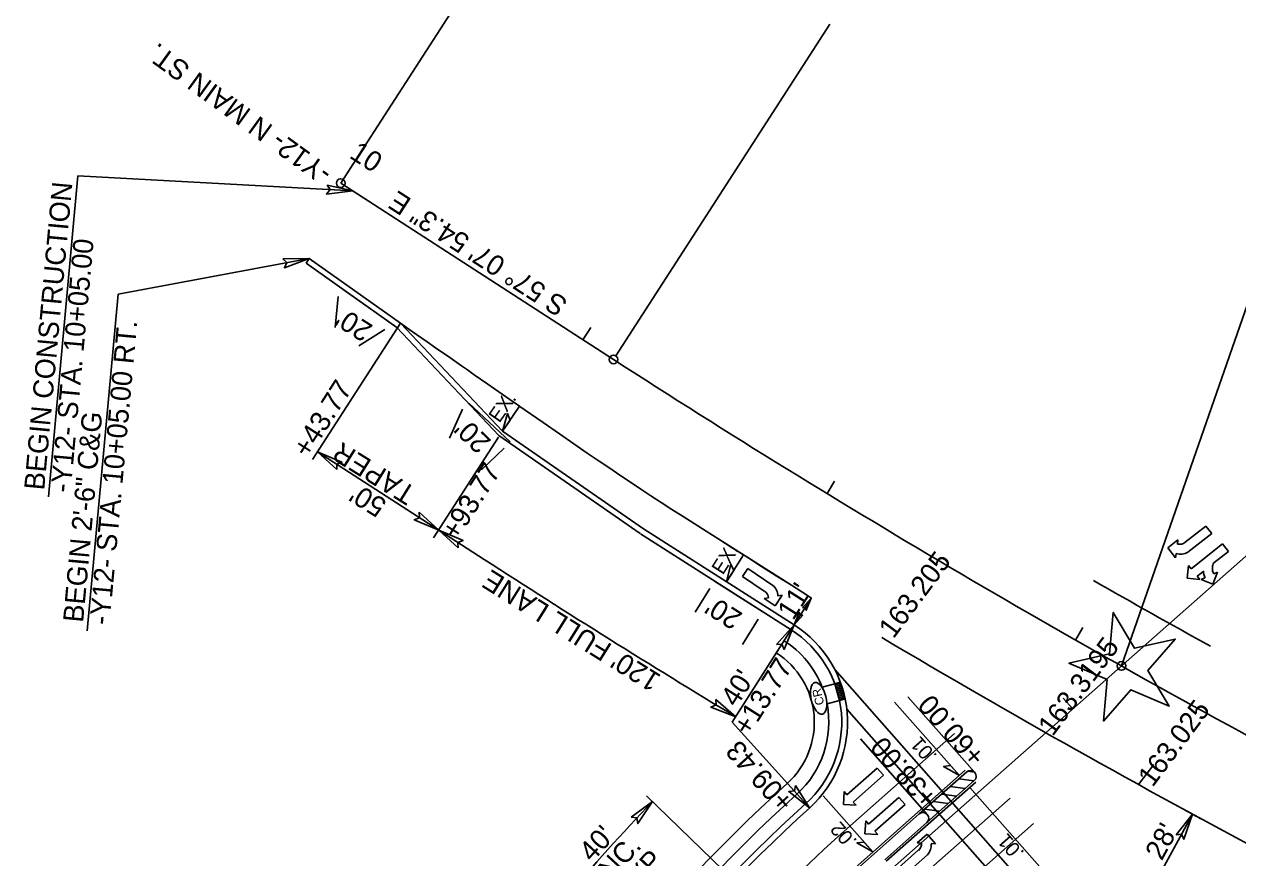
# Model space of a CAD drawing. Extents: x 2010838 to 2015151, y 441905 to 447792.
# Drawn here: x 2012526.5 to 2012947.2, y 446996.9 to 447285.7 of the extents above; entities that cross this region are included whole.
import ezdxf

# ---------------------------------------------------------------- set-up
doc = ezdxf.new("R2010")
doc.units = 0
for name, color, linetype in [('A-Wall-Abov', 7, 'Continuous'), ('A-Wall-Blow', 7, 'Continuous'), ('A-Wall-Comp', 7, 'Continuous'), ('B-Border', 7, 'Continuous'), ('B-Sheet Number', 7, 'Continuous'), ('C-Alignment Geometry', 7, 'Continuous'), ('C-Building', 7, 'Continuous'), ('C-CURB STOPS', 7, 'Continuous'), ('C-EOP 1', 7, 'Continuous'), ('C-Grave Plots', 7, 'Continuous'), ('C-SHBD-TEXT', 7, 'Continuous'), ('CLRD', 7, 'Continuous'), ('Cont-2-Lidar', 7, 'Continuous'), ('Default_10ft_LIDAR_Contou', 7, 'Continuous'), ('Default_2FT_LIDAR_Contour', 7, 'Continuous'), ('HATCH', 7, 'Continuous'), ('s-Existing Major', 7, 'Continuous'), ('S-Existing Minor', 7, 'Continuous'), ('S-overhead electric', 7, 'Continuous'), ('TEXT', 7, 'Continuous'), ('TEXT-LG', 7, 'Continuous'), ('TEXT-MED', 7, 'Continuous'), ('X2', 7, 'Continuous'), ('X4', 7, 'Continuous')]:
    doc.layers.add(name, color=color, linetype=linetype)

msp = doc.modelspace()

# ---------------------------------------------------------------- linework, layer by layer
at = {"layer": 'A-Wall-Abov'}
for p, q in [((2012928.92, 447106.22), (2012936.15, 447111.83)), ((2012936.15, 447111.83), (2012938.17, 447109.23)), ((2012922.9, 447104.27), (2012926.43, 447107.07)), ((2012926.43, 447107.07), (2012926.24, 447105.6)), ((2012938.17, 447109.23), (2012929.84, 447102.76)), ((2012941.85, 447105.64), (2012931.07, 447097.02)), ((2012943.91, 447103.06), (2012941.85, 447105.64)), ((2012925.64, 447100.83), (2012922.9, 447104.27)), ((2012925.82, 447102.3), (2012925.64, 447100.83)), ((2012938.87, 447099.03), (2012943.91, 447103.06)), ((2012930.13, 447098.19), (2012929.68, 447093.79)), ((2012931.07, 447097.02), (2012930.13, 447098.19)), ((2012775.43, 447094.39), (2012777.27, 447097.14)), ((2012783.03, 447089.3), (2012775.43, 447094.39)), ((2012777.27, 447097.14), (2012786.03, 447091.26)), ((2012929.68, 447093.79), (2012934.07, 447093.27)), ((2012933.13, 447094.44), (2012935.36, 447096.22)), ((2012934.07, 447093.27), (2012933.13, 447094.44)), ((2012935.81, 447093.89), (2012934.43, 447093.3)), ((2012934.43, 447093.3), (2012938.55, 447091.67)), ((2012938.55, 447091.67), (2012940.18, 447095.79)), ((2012940.18, 447095.79), (2012938.84, 447095.23)), ((2012783.01, 447086.67), (2012784.47, 447086.95)), ((2012786.78, 447084.2), (2012783.01, 447086.67)), ((2012789.19, 447087.89), (2012786.78, 447084.2)), ((2012787.73, 447087.6), (2012789.19, 447087.89)), ((2012811.69, 447018.67), (2012822.19, 447027.94)), ((2012822.19, 447027.94), (2012824.37, 447025.46)), ((2012824.37, 447025.46), (2012813.88, 447016.2)), ((2012810.45, 447015.31), (2012810.7, 447019.8)), ((2012810.7, 447019.8), (2012811.69, 447018.67)), ((2012819.17, 447008.52), (2012829.66, 447017.79)), ((2012829.66, 447017.79), (2012831.85, 447015.31)), ((2012814.87, 447015.07), (2012810.45, 447015.31)), ((2012813.88, 447016.2), (2012814.87, 447015.07)), ((2012831.85, 447015.31), (2012821.35, 447006.05)), ((2012817.93, 447005.16), (2012818.18, 447009.65)), ((2012818.18, 447009.65), (2012819.17, 447008.52)), ((2012822.35, 447004.92), (2012817.93, 447005.16)), ((2012821.35, 447006.05), (2012822.35, 447004.92)), ((2012839.46, 447005.02), (2012836.05, 447002.07)), ((2012842.33, 447001.68), (2012839.46, 447005.02)), ((2012836.05, 447002.07), (2012837.53, 447001.98)), ((2012840.85, 447001.78), (2012842.33, 447001.68)), ((2012836.42, 446999.47), (2012829.56, 446993.41)), ((2012831.75, 446990.94), (2012839.65, 446997.92))]:
    msp.add_line(p, q, dxfattribs=at)
for centre, radius, start, end in [((2012926.91, 447108.79), 3.28, 258.1586, 307.8167), ((2012927.29, 447107.33), 5.25, 253.829, 299.1407), ((2012942.8, 447097.24), 4.43, 176.0895, 206.9431), ((2012940.9, 447097.52), 2.52, 143.2676, 179.5796), ((2012939.77, 447095.92), 4.43, 176.1833, 207.0619), ((2012781.23, 447086.59), 3.28, 6.5226, 56.1808), ((2012782.49, 447087.4), 5.25, 2.193, 47.5047), ((2012834.27, 447001.92), 3.28, 311.4451, 1.1033), ((2012835.63, 447001.27), 5.25, 320.1212, 5.4329)]:
    msp.add_arc(centre, radius, start, end, dxfattribs=at)
at = {"layer": 'A-Wall-Blow'}
for p, q in [((2012698.21, 447153.33), (2012692.25, 447144.74)), ((2012775.88, 447101.83), (2012769.95, 447092.49)), ((2012850.65, 447025.37), (2012828.15, 447050.85)), ((2012803.39, 447018.33), (2012820.64, 446998.89)), ((2012881.11, 446990.87), (2012854.28, 447021.26))]:
    msp.add_line(p, q, dxfattribs=at)
at = {"layer": 'A-Wall-Comp'}
for points in [[(2012692.25, 447144.74), (2012694.03, 447150.81), (2012694.89, 447148.54)], [(2012769.95, 447092.49), (2012771.48, 447098.63), (2012772.43, 447096.4)], [(2012850.65, 447025.37), (2012845.18, 447028.54), (2012847.59, 447028.83)], [(2012820.64, 446998.89), (2012815.16, 447002.05), (2012817.57, 447002.35)]]:
    msp.add_lwpolyline(points, close=True, dxfattribs=at)
at = {"layer": 'B-Border'}
for radius, start, end in [(3308.24, 240.27502, 241.0786), (3362.24, 239.35482, 242.0055)]:
    msp.add_arc((2014537.56, 449965.84), radius, start, end, dxfattribs=at)
at = {"layer": 'B-Sheet Number'}
for p, q in [((2012635.31, 447191.33), (2012634.29, 447180.66)), ((2012635.31, 447191.33), (2012635.31, 447191.33)), ((2012651.47, 447179.9), (2012642.48, 447174.24)), ((2012651.47, 447179.9), (2012651.47, 447179.9))]:
    msp.add_line(p, q, dxfattribs=at)
at = {"layer": 'C-Alignment Geometry'}
for p, q in [((2012873.97, 446986.8), (2012807.45, 447062.13)), ((2012868.96, 446983.42), (2012811.63, 447048.33)), ((2012853.19, 447026.64), (2012836.7, 447012.08)), ((2012853.46, 447026.84), (2012855.99, 447026.5)), ((2012839.35, 447009.08), (2012855.84, 447023.65)), ((2012847.48, 447021.6), (2012852.72, 447020.89)), ((2012850.45, 447024.22), (2012855.69, 447023.51)), ((2012844.51, 447018.98), (2012849.75, 447018.26)), ((2012838.57, 447013.73), (2012843.8, 447013.02)), ((2012841.54, 447016.35), (2012846.78, 447015.64))]:
    msp.add_line(p, q, dxfattribs=at)
msp.add_arc((2012854.52, 447025.14), 2, 311.4451, 131.4451, dxfattribs=at)
at = {"layer": 'C-Building'}
for p, q in [((2012720.18, 447176.38), (2012722.89, 447180.58)), ((2012804.78, 447123.08), (2012807.38, 447127.35)), ((2012890.94, 447072.32), (2012893.41, 447076.67)), ((2012889.97, 447048.45), (2012886.66, 447052.2))]:
    msp.add_line(p, q, dxfattribs=at)
at = {"layer": 'C-CURB STOPS'}
for p, q in [((2012822.14, 446999.23), (2012836.7, 447012.08)), ((2012839.35, 447009.08), (2012824.79, 446996.23))]:
    msp.add_line(p, q, dxfattribs=at)
for centre, radius, start, end in [((2012838.03, 447010.58), 2, 311.4451, 131.4451), ((2013181.56, 446592.2), 543, 131.4451, 175.4266), ((2013181.56, 446592.2), 543, 131.4451, 175.4266)]:
    msp.add_arc(centre, radius, start, end, dxfattribs=at)
at = {"layer": 'C-EOP 1'}
msp.add_line((2012636.18, 447230.65), (2012640.53, 447237.37), dxfattribs=at)
at = {"layer": 'C-SHBD-TEXT'}
msp.add_line((2012912.8, 447022.24), (2012918.02, 447029.22), dxfattribs=at)
at = {"layer": 'CLRD'}
for p, q in [((2012636.18, 447230.65), (2012730.75, 447169.55)), ((2012636.18, 447230.65), (2012730.75, 447169.55)), ((2012827.44, 446993.23), (2013068.81, 447206.37))]:
    msp.add_line(p, q, dxfattribs=at)
msp.add_arc((2014537.56, 449965.84), 3329.24, 237.13174, 242.0055, dxfattribs=at)
msp.add_arc((2014537.56, 449965.84), 3329.24, 237.13174, 242.0055, dxfattribs=at)
at = {"layer": 'Default_10ft_LIDAR_Contou'}
for p, q in [((2012906.83, 447063.34), (2013011.33, 447363.33)), ((2012637, 447231.91), (2012711.21, 447346.77)), ((2012731.57, 447170.81), (2012805.78, 447285.67))]:
    msp.add_line(p, q, dxfattribs=at)
for centre in [(2012636.18, 447230.65), (2012730.75, 447169.55), (2012906.83, 447063.34)]:
    msp.add_circle(centre, 1.5, dxfattribs=at)
at = {"layer": 'HATCH'}
for p, q in [((2012792.47, 447091.3), (2012767.24, 447107.32)), ((2012813.7, 447008.78), (2012848.94, 447039.9)), ((2012821.65, 446999.79), (2012852.7, 447027.21)), ((2012825.29, 446995.66), (2012856.34, 447023.08)), ((2012833.23, 446986.67), (2012868.23, 447017.57)), ((2012841.17, 446977.67), (2012876.41, 447008.79))]:
    msp.add_line(p, q, dxfattribs=at)
for points in [[(2012656.91, 447182.17), (2012660.66, 447179.51), (2012666.12, 447175.67), (2012669.09, 447173.6), (2012673.98, 447170.19), (2012678.04, 447167.37), (2012680.15, 447165.89), (2012682.48, 447164.26), (2012687.19, 447160.99), (2012693.31, 447156.73), (2012698.21, 447153.33)], [(2012697.93, 447153.52), (2012706.33, 447147.7), (2012711.98, 447143.77), (2012717.03, 447140.27), (2012721.66, 447137.12), (2012725.82, 447134.3), (2012729.48, 447131.82), (2012732.97, 447129.46), (2012736.63, 447126.99), (2012740.27, 447124.55), (2012743.74, 447122.27), (2012747.24, 447120), (2012750.98, 447117.61), (2012754.86, 447115.15), (2012758.77, 447112.67), (2012762.86, 447110.1), (2012767.24, 447107.32), (2012771.93, 447104.33), (2012776.96, 447101.1), (2012782.1, 447097.81), (2012787.15, 447094.61), (2012792.47, 447091.3), (2012797.66, 447087.97), (2012799.45, 447086.8)]]:
    msp.add_lwpolyline(points, dxfattribs=at)
for centre, radius, start, end in [((2014537.56, 449965.84), 3362.24, 241.41262, 241.52803), ((2013181.56, 446592.2), 555.75, 131.4451, 175.4266), ((2013181.56, 446592.2), 543.75, 131.4451, 175.4266)]:
    msp.add_arc(centre, radius, start, end, dxfattribs=at)
at = {"layer": 's-Existing Major'}
for points in [[(2012631.48, 447229.98), (2012640.38, 447227.94), (2012631.26, 447226.84), (2012632.5, 447228.38)], [(2012616.14, 447204.42), (2012625.27, 447204.55), (2012616.67, 447201.31), (2012617.51, 447203.1)], [(2012634.87, 447131.38), (2012628.15, 447137.57), (2012636.62, 447134), (2012634.79, 447133.28)], [(2012663.43, 447116.62), (2012670.15, 447110.43), (2012661.68, 447114), (2012663.51, 447114.72)], [(2012676.86, 447104.25), (2012670.15, 447110.43), (2012678.62, 447106.87), (2012676.78, 447106.15)], [(2012796.24, 447083.51), (2012799.31, 447086.89), (2012797.56, 447082.64), (2012797.19, 447083.55)], [(2012796.45, 447080.94), (2012793.38, 447077.56), (2012795.14, 447081.81), (2012795.5, 447080.89)], [(2012787.25, 447070.79), (2012793.38, 447077.56), (2012789.88, 447069.06), (2012789.15, 447070.89)], [(2012766.21, 447051.73), (2012773.11, 447045.74), (2012764.54, 447049.06), (2012766.35, 447049.83)], [(2012793.86, 447021.9), (2012798.76, 447014.19), (2012791.49, 447019.82), (2012793.45, 447020.05)], [(2012736.92, 447010.98), (2012744.3, 447016.36), (2012739.15, 447008.75), (2012738.8, 447010.69)], [(2012925.79, 447004.86), (2012931.45, 447012.02), (2012928.53, 447003.31), (2012927.68, 447005.08)]]:
    msp.add_lwpolyline(points, close=True, dxfattribs=at)
at = {"layer": 'S-Existing Minor'}
for p, q in [((2012534.84, 447121.97), (2012545.07, 447233.21)), ((2012640.38, 447227.94), (2012545.07, 447233.21)), ((2012625.27, 447204.55), (2012559, 447192.15)), ((2012559, 447192.15), (2012548.28, 447075.55)), ((2012626.39, 447134.84), (2012656.95, 447182.14)), ((2012668.41, 447107.74), (2012690.93, 447142.6)), ((2012628.15, 447137.57), (2012670.15, 447110.43)), ((2012670.15, 447110.43), (2012685.95, 447100.22)), ((2012799.31, 447086.89), (2012793.38, 447077.56)), ((2012793.38, 447077.56), (2012771.89, 447043.83)), ((2012856.02, 447026.47), (2012832.85, 447052.7)), ((2012771.89, 447043.83), (2012798.76, 447014.19)), ((2012839.53, 447011.91), (2012816.36, 447038.14)), ((2012772.61, 446988.9), (2012742.23, 447018.37)), ((2012931.45, 447012.02), (2012918.08, 446987.42))]:
    msp.add_line(p, q, dxfattribs=at)
for centre, radius, start, end in [((2014537.56, 449965.84), 3411.78, 237.13174, 238.85785), ((2013182.44, 446591.46), 610.33, 135.8789, 140.15462)]:
    msp.add_arc(centre, radius, start, end, dxfattribs=at)
at = {"layer": 'S-overhead electric'}
for p, q in [((2012656.95, 447182.14), (2012625.27, 447204.55)), ((2012656.95, 447182.14), (2012692.29, 447144.7)), ((2012678.44, 447152.36), (2012673.88, 447142.32)), ((2012692.29, 447144.7), (2012741.15, 447110.84)), ((2012692.87, 447138.82), (2012685.02, 447131.24)), ((2012741.15, 447110.84), (2012793.38, 447077.56)), ((2012764.18, 447090.24), (2012759.09, 447081.98)), ((2012780.87, 447079.61), (2012775.52, 447070.81))]:
    msp.add_line(p, q, dxfattribs=at)
for centre, radius, start, end in [((2012771.89, 447043.83), 40, 312.2108, 57.4949), ((2013181.56, 446592.2), 569.75, 132.2108, 169.9194)]:
    msp.add_arc(centre, radius, start, end, dxfattribs=at)
at = {"layer": 'TEXT'}
msp.add_lwpolyline([(2012901.89, 447058.6), (2012900.58, 447044.24), (2012910.08, 447055.09), (2012923.36, 447049.38), (2012915.97, 447061.8), (2012925.48, 447072.66), (2012911.41, 447069.47), (2012904.03, 447081.87), (2012902.71, 447067.5), (2012888.62, 447064.3), (2012901.89, 447058.6)], dxfattribs=at)
at = {"layer": 'TEXT-LG'}
for p, q in [((2012807.47, 447057.19), (2012803.12, 447055.94)), ((2012807.47, 447057.19), (2012809.39, 447057.75)), ((2012807.47, 447057.19), (2012809.13, 447051.43)), ((2012809.39, 447057.75), (2012811.05, 447051.98)), ((2012809.13, 447051.43), (2012804.78, 447050.18)), ((2012811.05, 447051.98), (2012809.13, 447051.43))]:
    msp.add_line(p, q, dxfattribs=at)
for centre in [(2012807.82, 447056.89), (2012807.98, 447056.34), (2012808.14, 447055.76), (2012808.3, 447055.21), (2012808.35, 447057.05), (2012808.51, 447056.5), (2012808.67, 447055.92), (2012808.8, 447057.17), (2012808.83, 447055.37), (2012808.95, 447056.62), (2012809.12, 447056.05), (2012809.21, 447057.3), (2012809.28, 447055.49), (2012809.36, 447056.75), (2012809.53, 447056.17), (2012809.69, 447055.62), (2012808.47, 447054.63), (2012808.64, 447054.05), (2012808.8, 447053.47), (2012808.96, 447052.92), (2012809, 447054.79), (2012809.12, 447052.34), (2012809.17, 447054.21), (2012809.28, 447051.79), (2012809.33, 447053.63), (2012809.44, 447054.92), (2012809.49, 447053.08), (2012809.61, 447054.33), (2012809.65, 447052.5), (2012809.77, 447053.75), (2012809.81, 447051.95), (2012809.85, 447055.04), (2012809.93, 447053.2), (2012810.02, 447054.46), (2012810.1, 447052.63), (2012810.18, 447053.88), (2012810.25, 447052.07), (2012810.34, 447053.33), (2012810.51, 447052.75), (2012810.66, 447052.2)]:
    msp.add_circle(centre, 0.0869, dxfattribs=at)
for centre, radius, start, end in [((2012771.89, 447043.83), 33.5, 21.203, 57.4949), ((2012771.89, 447043.83), 28.5, 312.2108, 57.4949), ((2012771.89, 447043.83), 33.5, 312.2108, 10.9281), ((2013181.56, 446592.2), 581.25, 132.20083, 172.15843), ((2013181.56, 446592.2), 576.25, 132.20083, 171.53405)]:
    msp.add_arc(centre, radius, start, end, dxfattribs=at)
at = {"layer": 'TEXT-MED'}
for p, q in [((2012625.27, 447204.55), (2012624.19, 447202.87)), ((2012655.63, 447180.63), (2012624.19, 447202.87)), ((2012655.63, 447180.63), (2012690.98, 447143.18)), ((2012690.98, 447143.18), (2012740.01, 447109.2)), ((2012740.08, 447109.16), (2012792.31, 447075.87))]:
    msp.add_line(p, q, dxfattribs=at)
for centre, radius, start, end in [((2012771.89, 447043.83), 38, 312.2108, 57.4949), ((2013181.56, 446592.2), 571.75, 132.2008, 169.9194)]:
    msp.add_arc(centre, radius, start, end, dxfattribs=at)
at = {"layer": 'X2'}
for p, q in [((2012653.2, 447182.35), (2012637.04, 447193.78)), ((2012694.92, 447141.01), (2012680.5, 447154.55)), ((2012782.48, 447082.14), (2012765.79, 447092.77))]:
    msp.add_line(p, q, dxfattribs=at)
at = {"layer": 'X4'}
msp.add_ellipse((2012801.86, 447052.11), major_axis=(-1.31, 5.45), ratio=0.462467, dxfattribs=at)

# ---------------------------------------------------------------- texts
at = {"layer": 'A-Wall-Blow'}
for s, rotation, p in [('EX.', 55.253, (2012691.2, 447147.3)), ('EX.', 57.574, (2012768.66, 447094.64)), ('.01', 131.4451, (2012843.19, 447032.35)), ('.02', 131.587, (2012815.43, 447002.88)), ('.01', 131.4451, (2012873.41, 446998.74))]:
    msp.add_text(s, height=5, rotation=rotation, dxfattribs=at).set_placement(p)
at = {"layer": 'C-Grave Plots'}
for s, rotation, p in [('-Y12- N MAIN ST.', 144.0712, (2012633.76, 447235.34)), ('BEGIN CONSTRUCTION', 84.7467, (2012533.39, 447124.06)), ('-Y12- STA. 10+05.00', 84.7467, (2012542.53, 447123.22)), ("20'", 147.4949, (2012647.72, 447181.15)), ('+43.77', 57.574, (2012624.95, 447135.04)), ("20'", 136.1161, (2012688.69, 447141.37)), ('TAPER', 147.9948, (2012662.8, 447124.73)), ('+93.77', 57.574, (2012676.44, 447106.39)), ("50'", 147.9948, (2012652.61, 447120.37)), ("120' FULL LANE", 147.9948, (2012747.64, 447059.93)), ("11'", 57.574, (2012793.05, 447078.83)), ("20'", 147.4949, (2012775.89, 447081.4)), ('+13.77', 57.574, (2012777.61, 447038.74)), ("40'", 57.574, (2012773.36, 447048.77)), ('+09.43', 132.2008, (2012793.72, 447016.71)), ("28'", 61.4653, (2012920.83, 446995.59)), ("40'", 47.5064, (2012723.33, 446995.08)), ('INC. ', 47.5064, (2012728.19, 446986.92)), ('TYP', 47.5064, (2012736.18, 446982.17))]:
    msp.add_text(s, height=7, rotation=rotation, dxfattribs=at).set_placement(p)
at = {"layer": 'C-SHBD-TEXT'}
for s, p in [('163.205', (2012827.8, 447072.51)), ('163.3195', (2012883, 447038.67)), ('163.025', (2012917.64, 447021.07))]:
    msp.add_text(s, height=7, rotation=53.189, dxfattribs=at).set_placement(p)
at = {"layer": 'Cont-2-Lidar'}
msp.add_text('S 57%%d 07\' 54.3" E', height=7, rotation=147.1317, dxfattribs=at).set_placement((2012715.36, 447189.89))
at = {"layer": 'Default_2FT_LIDAR_Contour'}
msp.add_text('10', height=7, rotation=327.1317, dxfattribs=at).set_placement((2012638.83, 447239.64))
at = {"layer": 'S-Existing Minor'}
for s, rotation, p in [('-Y12- STA. 10+05.00 RT.', 84.7467, (2012556.02, 447077.38)), ('BEGIN 2\'-6" C&G', 84.7467, (2012546.88, 447078.22)), ('+60.00', 131.4451, (2012860.13, 447032.38)), ('+38.00', 131.4451, (2012843.64, 447017.82))]:
    msp.add_text(s, height=7, rotation=rotation, dxfattribs=at).set_placement(p)
at = {"layer": 'X4'}
msp.add_text('CR', height=3, rotation=103.4891, dxfattribs=at).set_placement((2012803.85, 447050.16))

doc.saveas('drawing.dxf')
